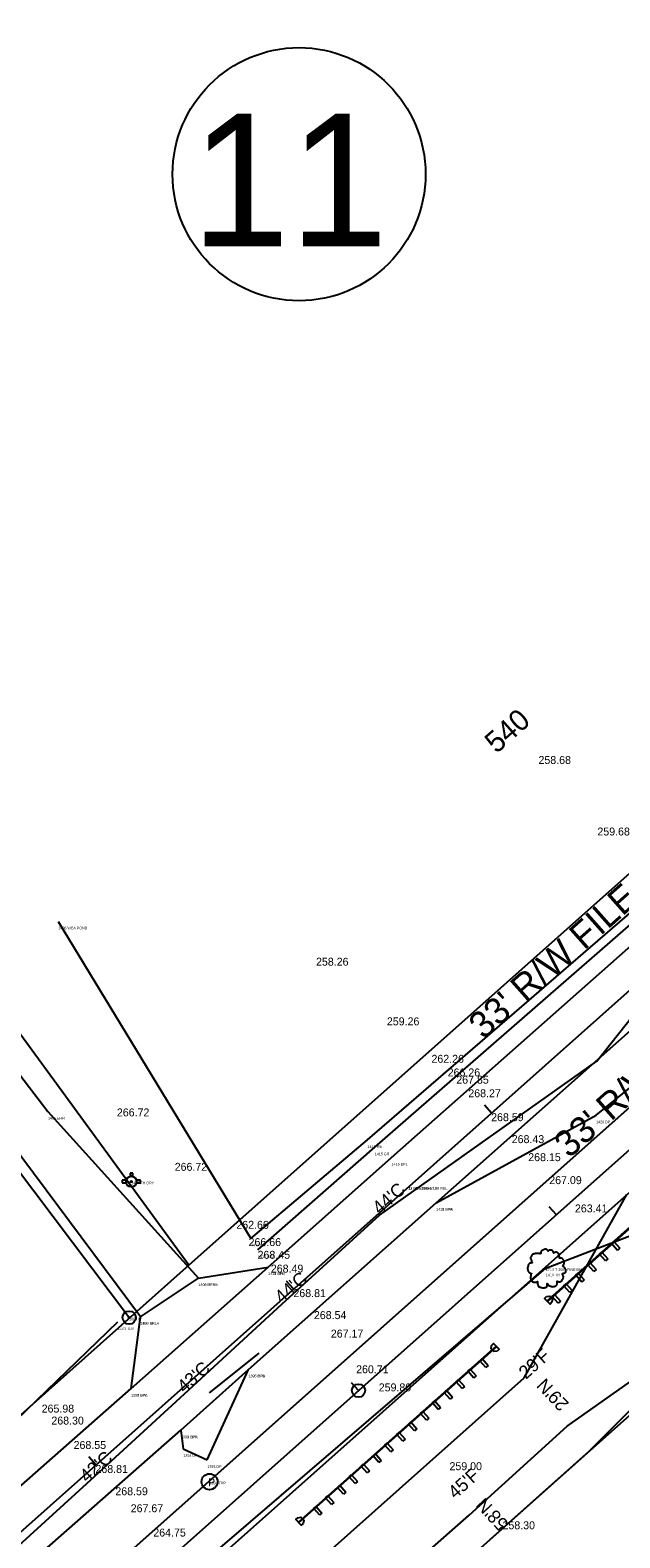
# Model space of a CAD drawing. Extents: x 49683 to 58852, y 49525 to 54803.
# Drawn here: x 54912 to 55135, y 52782 to 53351 of the extents above; entities that cross this region are included whole.
import ezdxf

# ---------------------------------------------------------------- set-up
doc = ezdxf.new("R2010")
doc.units = 0
for name, color, linetype in [('Level 1', 7, 'Continuous'), ('Level 10', 7, 'Continuous'), ('Level 11', 7, 'Continuous'), ('Level 12', 7, 'Continuous'), ('Level 13', 7, 'Continuous'), ('Level 18', 7, 'Continuous'), ('Level 19', 7, 'Continuous'), ('Level 20', 7, 'Continuous'), ('Level 21', 7, 'Continuous'), ('Level 25', 7, 'Continuous'), ('Level 27', 7, 'Continuous'), ('Level 3', 7, 'Continuous'), ('Level 32', 7, 'Continuous'), ('Level 33', 7, 'Continuous'), ('Level 34', 7, 'Continuous'), ('Level 48', 7, 'Continuous'), ('Level 51', 7, 'Continuous'), ('Level 53', 7, 'Continuous'), ('Level 57', 7, 'Continuous'), ('Level 58', 7, 'Continuous'), ('Level 59', 7, 'Continuous'), ('Level 60', 7, 'Continuous'), ('Level 61', 7, 'Continuous'), ('Level 62', 7, 'Continuous'), ('Level 7', 7, 'Continuous'), ('Level 8', 7, 'Continuous'), ('Level 9', 7, 'Continuous')]:
    doc.layers.add(name, color=color, linetype=linetype)

# ---------------------------------------------------------------- blocks, each defined once
blk = doc.blocks.new('TPP')
at = {"layer": 'Level 9'}
blk.add_circle((0, 0), 3, dxfattribs=at)
blk.add_text('P', height=3, dxfattribs=at).set_placement((-0.59, -1.73))
blk = doc.blocks.new('FH')
at = {"layer": 'Level 9'}
for p, q in [((-1.92, 0.57), (-3.47, 0.57)), ((-3.47, 0.57), (-3.47, -0.43)), ((-0.46, 3.22), (-0.46, 1.95)), ((0.54, 3.22), (-0.46, 3.22)), ((0.54, 1.92), (0.54, 3.22)), ((3.53, 0.57), (1.92, 0.57)), ((3.53, -0.43), (3.53, 0.57)), ((-3.47, -0.43), (-1.95, -0.43)), ((1.95, -0.43), (3.53, -0.43))]:
    blk.add_line(p, q, dxfattribs=at)
for radius in [2, 0.25]:
    blk.add_circle((0, 0), radius, dxfattribs=at)
for start, end in [(163.3387, 192.315), (74.2455, 103.2128), (347.685, 16.6613)]:
    blk.add_arc((0, 0), 2, start, end, dxfattribs=at)
blk = doc.blocks.new('T1')
at = {"layer": 'Level 11'}
for centre, radius in [((0, 0), 0.25), ((-0.01, -0.02), 0.0001)]:
    blk.add_circle(centre, radius, dxfattribs=at)
for points in [[(0.13, 7.17), (-0.17, 7.19), (-0.49, 7.09), (-0.74, 6.99), (-0.97, 6.92), (-1.19, 6.82), (-1.49, 6.64), (-1.72, 6.44), (-1.84, 6.19), (-1.89, 5.97), (-1.94, 5.69), (-1.94, 5.52), (-2.07, 5.49), (-2.22, 5.52), (-2.47, 5.59), (-2.72, 5.59), (-2.97, 5.59), (-3.32, 5.57), (-3.67, 5.57), (-3.94, 5.52), (-4.27, 5.47), (-4.64, 5.34), (-4.99, 5.22), (-5.29, 4.97), (-5.54, 4.49), (-5.67, 4.14), (-5.82, 3.89), (-5.67, 3.44), (-5.49, 3.09), (-5.47, 2.89), (-5.39, 2.47), (-5.29, 2.24), (-5.17, 2.04), (-5.24, 2.02), (-5.62, 1.97), (-5.92, 1.87), (-6.34, 1.64), (-6.57, 1.42), (-6.67, 1.09), (-6.69, 0.75), (-6.79, 0.55), (-6.87, 0.27), (-6.89, 0.2), (-6.94, -0.13), (-6.84, -0.58), (-6.82, -0.93), (-6.69, -1.15), (-6.54, -1.33), (-6.37, -1.58), (-5.97, -1.8), (-5.64, -1.9), (-5.44, -1.93), (-5.62, -2.43), (-5.67, -2.78), (-5.79, -3.18), (-5.79, -3.25), (-5.84, -3.73), (-5.69, -4.05), (-5.62, -4.43), (-5.44, -4.65), (-5.17, -4.95), (-4.84, -5.18), (-4.34, -5.3), (-3.94, -5.28), (-3.37, -5.1), (-3.12, -5.03), (-3.14, -5.2), (-3.12, -5.58), (-3.12, -6), (-2.97, -6.33), (-2.87, -6.6), (-2.72, -6.85), (-2.39, -7.08), (-1.99, -7.15), (-1.57, -7.3), (-1.12, -7.38), (-0.62, -7.4), (-0.02, -7.25), (0.26, -7.13), (0.36, -6.95), (0.56, -6.58), (0.51, -6.35), (0.53, -5.75), (0.63, -5.93), (0.81, -6.28), (1.31, -6.58), (1.71, -6.75), (2.18, -6.9), (2.48, -6.98), (2.96, -6.9), (3.33, -6.83), (3.71, -6.7), (4.01, -6.43), (4.18, -6.15), (4.23, -5.88), (4.31, -5.5), (4.36, -5.33)], [(4.36, -5.33), (4.28, -5.15), (4.23, -4.9), (4.31, -4.93), (4.48, -4.98), (4.75, -5.1), (4.98, -5.18), (5.3, -5.15), (5.58, -5.05), (6.03, -4.78), (6.3, -4.3), (6.58, -3.9), (6.65, -3.58), (6.6, -3.35), (6.58, -2.85), (6.38, -2.6), (6.33, -2.48), (6.23, -2.08), (6.3, -2.03), (6.58, -1.98), (6.95, -1.85), (7.23, -1.73), (7.45, -1.55), (7.53, -1.33), (7.5, -0.93), (7.55, -0.53), (7.48, -0.38), (7.38, -0.23), (7.3, -0.03), (7.15, 0.12), (7.05, 0.27), (6.95, 0.37), (6.83, 0.52), (6.65, 0.65), (6.5, 0.7), (6.45, 0.85), (6.6, 1.04), (6.65, 1.14), (6.68, 1.37), (6.9, 1.72), (6.95, 2.12), (6.9, 2.54), (6.85, 2.82), (6.7, 3.09), (6.5, 3.34), (6.38, 3.52), (6.2, 3.64), (5.88, 3.77), (5.63, 3.82), (5.28, 3.82), (5.08, 3.87), (5.1, 3.92), (5.1, 4.07), (5.1, 4.34), (5.03, 4.79), (4.88, 5.29), (4.88, 5.32), (4.78, 5.57), (4.56, 5.77), (4.38, 5.87), (4.18, 5.99), (3.93, 6.02), (3.63, 6.02), (3.36, 5.97), (3.16, 5.87), (2.98, 5.74), (2.91, 5.89), (2.81, 6.19), (2.76, 6.34), (2.61, 6.52), (2.38, 6.72), (1.93, 6.84), (1.31, 6.77), (1.01, 6.57), (0.86, 6.39), (0.81, 6.52), (0.61, 6.72), (0.51, 6.89), (0.33, 7.02), (0.18, 7.12), (0.08, 7.17)]]:
    blk.add_spline(points, degree=3, dxfattribs=at)
blk = doc.blocks.new('IP')
at = {"layer": 'Level 12'}
for radius in [2.5, 0.25]:
    blk.add_circle((0, 0), radius, dxfattribs=at)

msp = doc.modelspace()

# ---------------------------------------------------------------- linework, layer by layer
at = {"layer": 'Level 1'}
for p, q in [((52544.81, 50683.3), (55534.58, 53340.86)), ((55086.14, 52942.25), (55083.48, 52945.23)), ((55011.4, 52875.81), (55008.74, 52878.8)), ((54936.65, 52809.37), (54934, 52812.36))]:
    msp.add_line(p, q, dxfattribs=at)
at = {"layer": 'Level 10'}
for p, q in [((55039.31, 52932.12), (55223.63, 53091.32)), ((54922.47, 53014.66), (54995.29, 52894.87)), ((54995.29, 52894.87), (55039.31, 52932.12))]:
    msp.add_line(p, q, dxfattribs=at)
at = {"layer": 'Level 11'}
for p, q in [((55106.73, 52883.65), (55187.95, 52915.03)), ((54913.43, 52717.81), (55106.73, 52883.65)), ((54711.21, 52637.72), (54944.99, 52863.38))]:
    msp.add_line(p, q, dxfattribs=at)
at = {"layer": 'Level 12'}
for p, q in [((54949.37, 52864.83), (54608.23, 53316.46)), ((54971.79, 52884.76), (54817.75, 53095.57))]:
    msp.add_line(p, q, dxfattribs=at)
at = {"layer": 'Level 13'}
for p, q in [((54971.79, 52884.76), (55235.68, 53119.33)), ((55279.53, 53070), (53969.03, 51905.11)), ((54971.79, 52884.76), (53925.18, 51954.44))]:
    msp.add_line(p, q, dxfattribs=at)
at = {"layer": 'Level 18'}
for p, q in [((55125.98, 52961.91), (55157.54, 53001.67)), ((55084.95, 52932.81), (55125.98, 52961.91)), ((55043.92, 52903.71), (55084.95, 52932.81)), ((55006.97, 52870.02), (55043.92, 52903.71)), ((54970.15, 52836.18), (55006.97, 52870.02)), ((55114.77, 52824), (55155.86, 52853.04)), ((55123.14, 52814.59), (55158.52, 52850.05)), ((54933.3, 52802.37), (54970.15, 52836.18)), ((55077.8, 52790.34), (55114.77, 52824)), ((55085.77, 52781.37), (55123.14, 52814.59)), ((54896.29, 52768.76), (54933.3, 52802.37)), ((55040.18, 52757.39), (55077.8, 52790.34))]:
    msp.add_line(p, q, dxfattribs=at)
at = {"layer": 'Level 19'}
for p, q in [((54181.77, 52078.16), (56150.85, 53828.45)), ((55110.69, 52903.86), (55108.03, 52906.85)), ((55035.94, 52837.42), (55033.29, 52840.41))]:
    msp.add_line(p, q, dxfattribs=at)
msp.add_circle((55035.94, 52837.42), 2.5, dxfattribs=at)
at = {"layer": 'Level 20'}
for p, q in [((54173.8, 52087.13), (55269.45, 53061.04)), ((54189.74, 52069.19), (55278.86, 53037.3)), ((55098.56, 52842.24), (55137.34, 52911.5)), ((55023.82, 52775.8), (55098.56, 52842.24))]:
    msp.add_line(p, q, dxfattribs=at)
at = {"layer": 'Level 25'}
msp.add_circle((55013.46, 53296.85), 47.8, dxfattribs=at)
at = {"layer": 'Level 27'}
for p, q in [((55107.17, 52871.3), (55144.54, 52904.52)), ((55107.34, 52871.11), (55144.71, 52904.33)), ((55131.51, 52892.94), (55132.4, 52893.72)), ((55133.77, 52890.4), (55131.51, 52892.94)), ((55132.4, 52893.72), (55134.65, 52891.18)), ((55134.65, 52891.18), (55133.77, 52890.4)), ((55122.54, 52884.97), (55123.43, 52885.75)), ((55124.8, 52882.42), (55122.54, 52884.97)), ((55123.43, 52885.75), (55125.69, 52883.21)), ((55127.03, 52888.95), (55127.91, 52889.74)), ((55129.29, 52886.41), (55127.03, 52888.95)), ((55127.91, 52889.74), (55130.17, 52887.2)), ((55130.17, 52887.2), (55129.29, 52886.41)), ((55118.06, 52880.98), (55118.94, 52881.76)), ((55120.32, 52878.44), (55118.06, 52880.98)), ((55118.94, 52881.76), (55121.2, 52879.22)), ((55121.2, 52879.22), (55120.32, 52878.44)), ((55125.69, 52883.21), (55124.8, 52882.42)), ((55109.09, 52873.01), (55109.97, 52873.79)), ((55111.35, 52870.47), (55109.09, 52873.01)), ((55109.97, 52873.79), (55112.23, 52871.25)), ((55113.58, 52876.99), (55114.46, 52877.78)), ((55115.83, 52874.45), (55113.58, 52876.99)), ((55114.46, 52877.78), (55116.72, 52875.24)), ((55116.72, 52875.24), (55115.83, 52874.45)), ((55112.23, 52871.25), (55111.35, 52870.47)), ((55013.19, 52787.76), (55087.93, 52854.2)), ((55013.36, 52787.58), (55088.1, 52854.01)), ((55077.29, 52844.74), (55078.17, 52845.52)), ((55079.54, 52842.19), (55077.29, 52844.74)), ((55078.17, 52845.52), (55080.43, 52842.98)), ((55081.77, 52848.72), (55082.65, 52849.51)), ((55084.03, 52846.18), (55081.77, 52848.72)), ((55082.65, 52849.51), (55084.91, 52846.97)), ((55084.91, 52846.97), (55084.03, 52846.18)), ((55072.8, 52840.75), (55073.68, 52841.54)), ((55075.06, 52838.21), (55072.8, 52840.75)), ((55073.68, 52841.54), (55075.94, 52838.99)), ((55075.94, 52838.99), (55075.06, 52838.21)), ((55080.43, 52842.98), (55079.54, 52842.19)), ((55063.83, 52832.78), (55064.72, 52833.56)), ((55064.72, 52833.56), (55066.97, 52831.02)), ((55068.32, 52836.76), (55069.2, 52837.55)), ((55070.58, 52834.22), (55068.32, 52836.76)), ((55069.2, 52837.55), (55071.46, 52835.01)), ((55071.46, 52835.01), (55070.58, 52834.22)), ((55059.35, 52828.79), (55060.23, 52829.58)), ((55061.61, 52826.25), (55059.35, 52828.79)), ((55060.23, 52829.58), (55062.49, 52827.04)), ((55066.09, 52830.24), (55063.83, 52832.78)), ((55066.97, 52831.02), (55066.09, 52830.24)), ((55050.38, 52820.82), (55051.26, 52821.6)), ((55051.26, 52821.6), (55053.52, 52819.06)), ((55054.86, 52824.81), (55055.75, 52825.59)), ((55057.12, 52822.26), (55054.86, 52824.81)), ((55055.75, 52825.59), (55058.01, 52823.05)), ((55058.01, 52823.05), (55057.12, 52822.26)), ((55062.49, 52827.04), (55061.61, 52826.25)), ((55045.89, 52816.83), (55046.78, 52817.62)), ((55048.15, 52814.29), (55045.89, 52816.83)), ((55046.78, 52817.62), (55049.04, 52815.08)), ((55052.64, 52818.28), (55050.38, 52820.82)), ((55053.52, 52819.06), (55052.64, 52818.28)), ((55041.41, 52812.85), (55042.29, 52813.63)), ((55043.67, 52810.31), (55041.41, 52812.85)), ((55042.29, 52813.63), (55044.55, 52811.09)), ((55044.55, 52811.09), (55043.67, 52810.31)), ((55049.04, 52815.08), (55048.15, 52814.29)), ((55032.44, 52804.87), (55033.32, 52805.66)), ((55034.7, 52802.33), (55032.44, 52804.87)), ((55033.32, 52805.66), (55035.58, 52803.12)), ((55036.93, 52808.86), (55037.81, 52809.65)), ((55039.18, 52806.32), (55036.93, 52808.86)), ((55037.81, 52809.65), (55040.07, 52807.1)), ((55040.07, 52807.1), (55039.18, 52806.32)), ((55027.96, 52800.89), (55028.84, 52801.67)), ((55030.22, 52798.35), (55027.96, 52800.89)), ((55028.84, 52801.67), (55031.1, 52799.13)), ((55031.1, 52799.13), (55030.22, 52798.35)), ((55035.58, 52803.12), (55034.7, 52802.33)), ((55018.99, 52792.92), (55019.87, 52793.7)), ((55019.87, 52793.7), (55022.13, 52791.16)), ((55023.47, 52796.9), (55024.36, 52797.69)), ((55025.73, 52794.36), (55023.47, 52796.9)), ((55024.36, 52797.69), (55026.61, 52795.15)), ((55026.61, 52795.15), (55025.73, 52794.36)), ((55021.25, 52790.37), (55018.99, 52792.92)), ((55022.13, 52791.16), (55021.25, 52790.37))]:
    msp.add_line(p, q, dxfattribs=at)
for points in [[(55106.93, 52872.98), (55108.17, 52873.14), (55109.21, 52872.06), (55109.02, 52870.83), (55108.3, 52870.13), (55106.21, 52872.28)], [(55088.34, 52852.33), (55087.1, 52852.17), (55086.06, 52853.25), (55086.25, 52854.48), (55086.97, 52855.18), (55089.06, 52853.03)], [(55012.95, 52789.44), (55014.19, 52789.6), (55015.23, 52788.52), (55015.04, 52787.29), (55014.32, 52786.59), (55012.23, 52788.75)]]:
    msp.add_lwpolyline(points, close=True, dxfattribs=at)
at = {"layer": 'Level 3'}
for p, q in [((55048.41, 52925.43), (55227.38, 53083.78)), ((55065.24, 52908.36), (55241.71, 53064.82)), ((54855.23, 53025.4), (54918.56, 52942.82)), ((54918.56, 52942.82), (54975.4, 52879.91)), ((54953.51, 52865.35), (54904.33, 52931.37)), ((55001.77, 52884.07), (55048.41, 52925.43)), ((54994.31, 52845.45), (55065.24, 52908.36)), ((54949.96, 52838.18), (55001.77, 52884.07)), ((54968.8, 52822.44), (54994.31, 52845.45)), ((54897.27, 52791.82), (54949.96, 52838.18)), ((54914.07, 52774.35), (54968.8, 52822.44))]:
    msp.add_line(p, q, dxfattribs=at)
at = {"layer": 'Level 33'}
msp.add_line((54231.59, 52022.1), (55608.96, 53246.42), dxfattribs=at)
at = {"layer": 'Level 34'}
msp.add_line((54979.65, 52836.56), (54998.37, 52851.58), dxfattribs=at)
at = {"layer": 'Level 7'}
for p, q in [((55042.06, 52929.32), (55225.18, 53088.89)), ((54997.91, 52890.55), (55042.06, 52929.32))]:
    msp.add_line(p, q, dxfattribs=at)
at = {"layer": 'Level 8'}
for p, q in [((55125.68, 52941.41), (55179.24, 52985.05)), ((55065.24, 52908.36), (55125.68, 52941.41)), ((54975.4, 52879.91), (55001.77, 52884.07)), ((54953.51, 52865.35), (54975.4, 52879.91)), ((54949.96, 52838.18), (54953.51, 52865.35)), ((54978.78, 52811.23), (54994.31, 52845.45)), ((54968.8, 52822.44), (54969.71, 52815.44)), ((54969.71, 52815.44), (54978.78, 52811.23))]:
    msp.add_line(p, q, dxfattribs=at)

# ---------------------------------------------------------------- block references
at = {"layer": 'Level 11'}
msp.add_blockref('T1', (55106.73, 52883.65), dxfattribs=at)
at = {"layer": 'Level 12'}
msp.add_blockref('IP', (54949.25, 52864.99), dxfattribs=at)
at = {"layer": 'Level 9'}
for name, p in [('FH', (54950.06, 52916.37)), ('TPP', (54979.64, 52803.01))]:
    msp.add_blockref(name, p, dxfattribs=at)

# ---------------------------------------------------------------- texts
at = {"layer": 'Level 21'}
msp.add_text('540', height=8, rotation=41.6333, dxfattribs=at).set_placement((55088.08, 53077.77))
at = {"layer": 'Level 25'}
msp.add_text('11', height=50, dxfattribs=at).set_placement((54972.69, 53269.66))
for p in [(55083.2, 52969.74), (55115.53, 52924.89)]:
    msp.add_text("33' R/W FILE # 408-B", height=10, rotation=41.6333, dxfattribs=at).set_placement(p)
at = {"layer": 'Level 32'}
for s, p in [('258.68', (55103.95, 53074.1)), ('259.68', (55126.21, 53047.09)), ('258.26', (55019.87, 52997.92)), ('259.26', (55046.66, 52975.4)), ('262.26', (55063.5, 52961.25)), ('266.26', (55069.63, 52956.1)), ('267.85', (55072.88, 52953.36)), ('268.27', (55077.43, 52948.23)), ('266.72', (54944.62, 52941)), ('268.59', (55086.06, 52939.19)), ('268.43', (55093.84, 52930.9)), ('268.15', (55100.08, 52924.09)), ('266.72', (54966.47, 52920.45)), ('267.09', (55108.02, 52915.42)), ('263.41', (55117.72, 52904.74)), ('262.66', (54989.76, 52898.55)), ('266.66', (54994.39, 52892.02)), ('268.45', (54997.79, 52887.22)), ('268.49', (55002.8, 52882.01)), ('268.81', (55011.34, 52872.74)), ('268.54', (55019.07, 52864.44)), ('267.17', (55025.47, 52857.46)), ('260.71', (55035.03, 52843.98)), ('259.80', (55043.58, 52837.14)), ('265.98', (54916.19, 52829.14)), ('268.30', (54919.86, 52824.61)), ('268.55', (54928.26, 52815.39)), ('259.00', (55070.31, 52807.38)), ('268.81', (54936.52, 52806.32)), ('268.59', (54944.04, 52797.91)), ('267.67', (54949.84, 52791.49)), ('258.30', (55090.35, 52785.06)), ('264.75', (54958.38, 52782.31))]:
    msp.add_text(s, height=3, dxfattribs=at).set_placement(p)
at = {"layer": 'Level 48'}
for s, rotation, p in [("44'C", 41.6334, (55043.92, 52903.71)), ("44'C", 41.6334, (55006.97, 52870.02)), ("29'F", 41.6334, (55099.23, 52841.49)), ("43'C", 41.6334, (54970.15, 52836.18)), ("29'N", 132.8528, (55115.75, 52832.56)), ("42'C", 41.6334, (54933.3, 52802.37)), ("45'F", 41.6334, (55072.51, 52796.28)), ("58'N", 132.8528, (55092.82, 52787.44))]:
    msp.add_text(s, height=5, rotation=rotation, dxfattribs=at).set_placement(p)
at = {"layer": 'Level 51'}
for s in ['32 PT 538+66.21', '13 POT 538+57.98 REL']:
    msp.add_text(s, height=1, dxfattribs=at).set_placement((55054.73, 52913.33))
at = {"layer": 'Level 53'}
for s, p in [('1405 ERR', (54918.56, 52939.82)), ('1416 EPL', (55048.41, 52922.43)), ('1417 EPR', (55065.24, 52905.36)), ('1411 EPL', (55001.77, 52881.07)), ('1408 ERRB', (54975.4, 52876.91)), ('1400 ERLA', (54953.51, 52862.35)), ('1396 EPR', (54994.31, 52842.45)), ('1397 EPL', (54949.96, 52835.18)), ('1390 EPR', (54968.8, 52819.44))]:
    msp.add_text(s, height=1, dxfattribs=at).set_placement(p)
at = {"layer": 'Level 57'}
for s, p in [('1415 GR', (55042.06, 52926.32)), ('1412 GRA', (54997.91, 52887.55))]:
    msp.add_text(s, height=1, dxfattribs=at).set_placement(p)
at = {"layer": 'Level 58'}
for s, p in [('1420 DP', (55125.68, 52938.41)), ('1418 DPA', (55065.24, 52905.36)), ('1410 DPB', (55001.77, 52881.07)), ('1409 DP', (54975.4, 52876.91)), ('1399 DP', (54953.51, 52862.35)), ('1395 DPB', (54994.31, 52842.45)), ('1398 DPA', (54949.96, 52835.18)), ('1391 DPA', (54968.8, 52819.44)), ('1392 DP', (54969.71, 52812.44)), ('1393 DP', (54978.78, 52808.23))]:
    msp.add_text(s, height=1, dxfattribs=at).set_placement(p)
at = {"layer": 'Level 59'}
for s, p in [('1407 FH DRY', (54950.06, 52915.37)), ('1394 TPP', (54979.64, 52802.01))]:
    msp.add_text(s, height=1, dxfattribs=at).set_placement(p)
at = {"layer": 'Level 60'}
for s, p in [('1406 WEA POND', (54922.47, 53011.66)), ('1414 WE ', (55039.31, 52929.12)), ('1413 WE ', (54995.29, 52891.87))]:
    msp.add_text(s, height=1, dxfattribs=at).set_placement(p)
at = {"layer": 'Level 61'}
for s, p in [('1713 T 30IN PINE BM 7', (55106.73, 52882.65)), ('1419 TR', (55106.73, 52880.65)), ('1401 TLB', (54944.99, 52860.38))]:
    msp.add_text(s, height=1, dxfattribs=at).set_placement(p)
at = {"layer": 'Level 62'}
msp.add_text('1009 IP', height=1, dxfattribs=at).set_placement((54949.25, 52863.99))

doc.saveas('drawing.dxf')
